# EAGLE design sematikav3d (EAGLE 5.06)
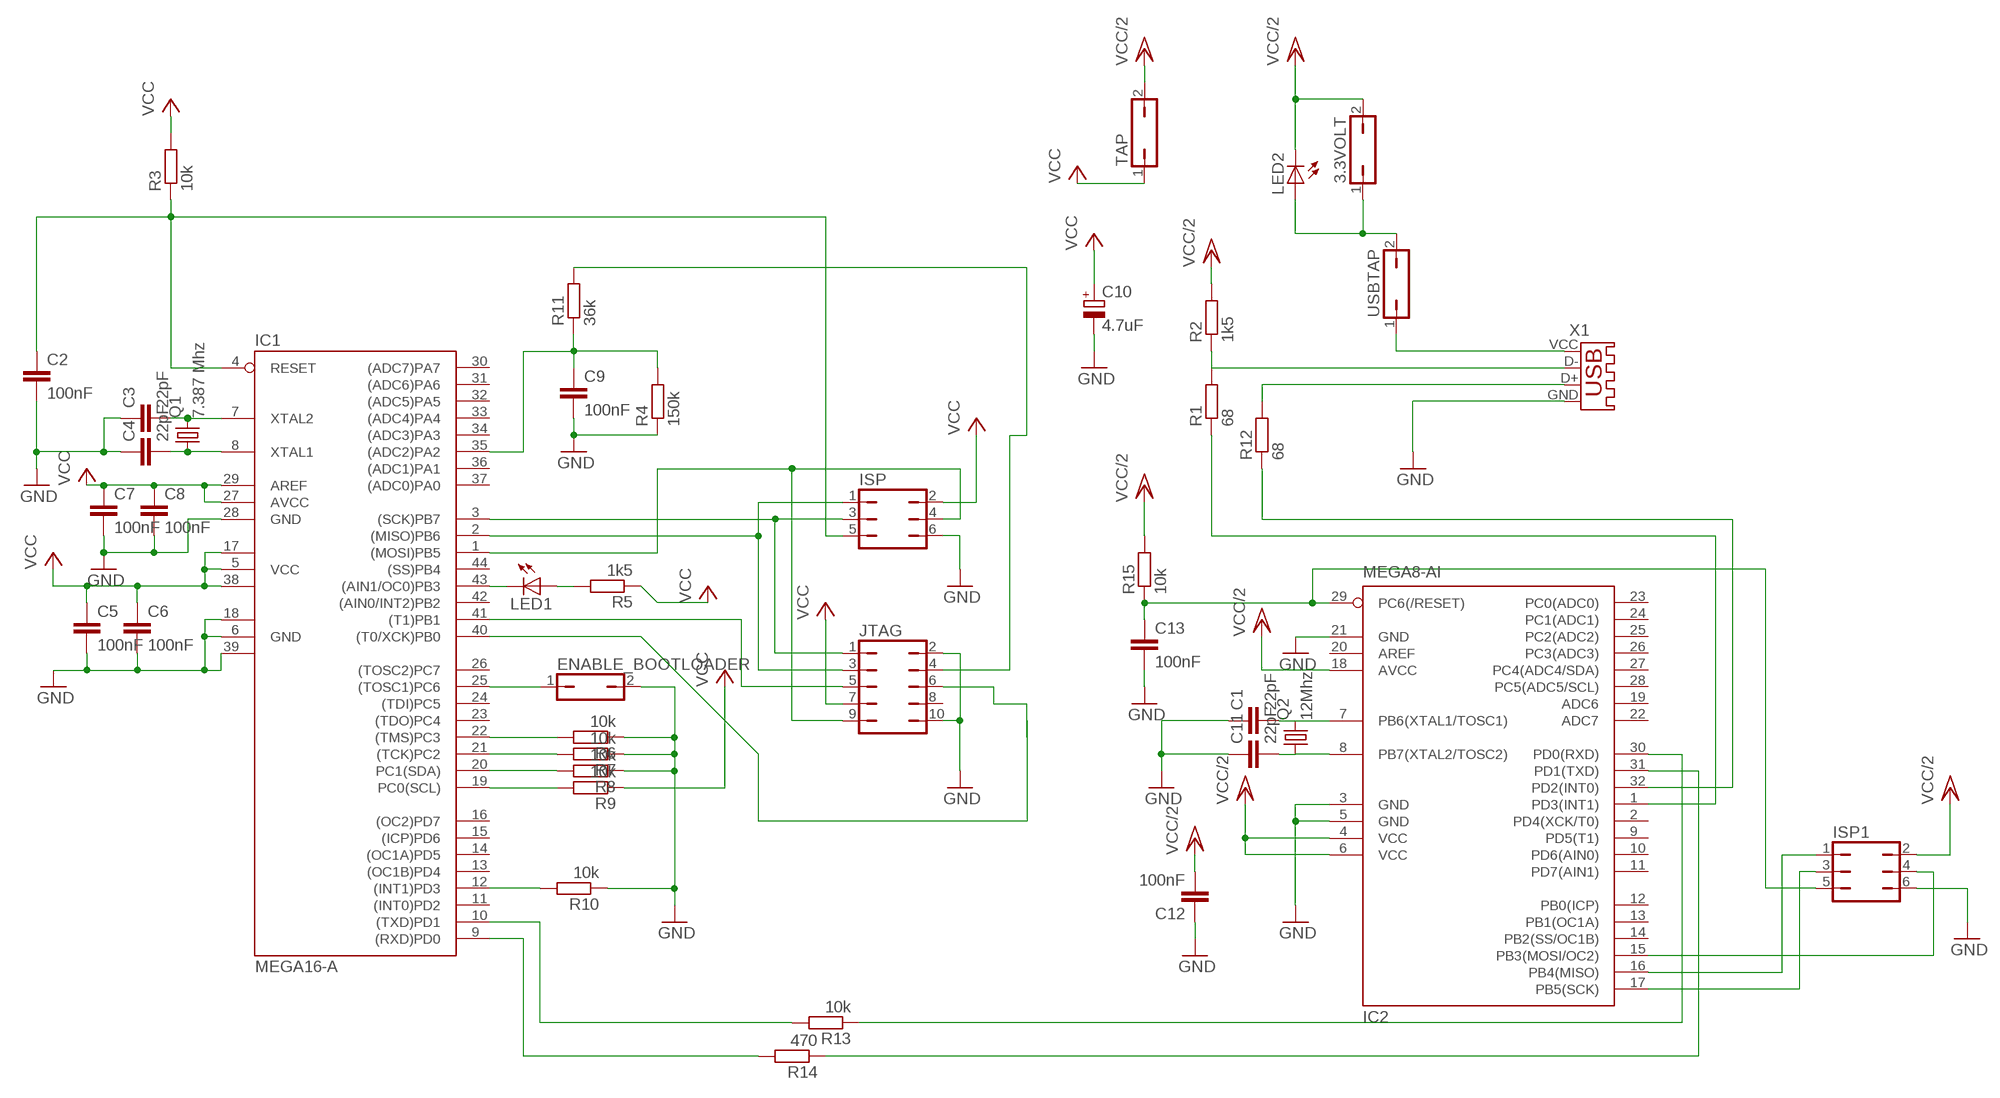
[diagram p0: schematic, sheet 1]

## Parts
3.3VOLT  JP1Q  [JP1]
C1  22pF  C-EUC1206  [C1206]
C2  100nF  C-EUC1206  [C1206]
C3  22pF  C-EUC1206  [C1206]
C4  22pF  C-EUC1206  [C1206]
C5  100nF  C-EUC1206  [C1206]
C6  100nF  C-EUC1206  [C1206]
C7  100nF  C-EUC1206  [C1206]
C8  100nF  C-EUC1206  [C1206]
C9  100nF  C-EUC1206  [C1206]
C10  4.7uF  CPOL-EUE2,5-6E  [E2,5-6E]
C11  22pF  C-EUC1206  [C1206]
C12  100nF  C-EUC1206  [C1206]
C13  100nF  C-EUC1206  [C1206]
ENABLE_BOOTLOADER  JP1Q  [JP1]
IC1  MEGA16-A  [TQFP44]
IC2  MEGA8-AI  [TQFP32-08]
ISP  JP3Q  [JP3Q]
ISP1  JP3Q  [JP3Q]
JTAG  JP5Q  [JP5Q]
LED1  LED3MM  [LED3MM]
LED2  LED5MM  [LED5MM]
Q1  7.387 Mhz  CRYSTALHC49U-V  [HC49U-V]
Q2  12Mhz  CRYSTALHC49U-V  [HC49U-V]
R1  68  R-EU_R1206  [R1206]
R2  1k5  R-EU_R1206  [R1206]
R3  10k  R-EU_R1206  [R1206]
R4  150k  R-EU_R1206  [R1206]
R5  1k5  R-EU_R1206  [R1206]
R6  10k  R-EU_R1206  [R1206]
R7  10k  R-EU_R1206  [R1206]
R8  10k  R-EU_R1206  [R1206]
R9  10k  R-EU_R1206  [R1206]
R10  10k  R-EU_R1206  [R1206]
R11  36k  R-EU_R1206  [R1206]
R12  68  R-EU_R1206  [R1206]
R13  10k  R-EU_R1206  [R1206]
R14  470  R-EU_R1206  [R1206]
R15  10k  R-EU_R1206  [R1206]
TAP  JP1Q  [JP1]
USBTAP  JP1Q  [JP1]
X1  USB-A003  [USB-A003]

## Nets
GND: C1.1 C2.2 C3.1 C4.1 C5.2 C6.2 C7.2 C8.2 C9.2 C10.- C11.1 C12.1 C13.2 ENABLE_BOOTLOADER.2 IC1.6(GND) IC1.18(GND1) IC1.28(GND) IC1.39(GND2) IC2.3(GND) IC2.5(GND) IC2.21(GND) ISP1.6 ISP.6 JTAG.2 JTAG.10 R4.1 R6.1 R7.1 R8.1 R10.1 X1.GND
N$1: 3.3VOLT.1 LED2.A USBTAP.2
N$2: IC2.1(PD3(INT1)) R1.1
N$3: R1.2 R2.1 X1.D-
N$4: R12.2 X1.D+
N$5: IC2.32(PD2(INT0)) R12.1
N$6: C11.2 IC2.8(PB7(XTAL2/TOSC2)) Q2.1
N$7: C1.2 IC2.7(PB6(XTAL1/TOSC1)) Q2.2
N$8: C2.1 IC1.4(RESET) ISP.5 R3.1
N$9: IC1.22((TMS)PC3) R6.2
N$10: C3.2 IC1.7(XTAL2) Q1.2
N$11: C4.2 IC1.8(XTAL1) Q1.1
N$12: C9.1 IC1.35((ADC2)PA2) R4.2 R11.1
N$13: IC1.21((TCK)PC2) R7.2
N$14: IC1.43((AIN1/OC0)PB3) LED1.K(C)
N$15: LED1.A R5.2
N$16: ENABLE_BOOTLOADER.1 IC1.25((TOSC1)PC6)
N$17: IC1.20(PC1(SDA)) R8.2
N$18: IC1.19(PC0(SCL)) R9.2
N$19: IC1.12((INT1)PD3) R10.2
N$20: IC1.1((MOSI)PB5) ISP.4 JTAG.9
N$21: IC1.3((SCK)PB7) ISP.3 JTAG.1
N$22: IC1.2((MISO)PB6) ISP.1 JTAG.3
N$24: IC1.41((T1)PB1) JTAG.5
N$27: IC1.40((T0/XCK)PB0) JTAG.6
N$28: JTAG.4 R11.2
N$37: USBTAP.1 X1.VCC
N$38: IC2.31(PD1(TXD)) R14.1
N$39: IC1.9((RXD)PD0) R14.2
N$40: IC2.30(PD0(RXD)) R13.1
N$41: IC1.10((TXD)PD1) R13.2
N$42: IC2.16(PB4(MISO)) ISP1.1
N$43: IC2.17(PB5(SCK)) ISP1.3
N$44: IC2.15(PB3(MOSI/OC2)) ISP1.4
N$45: C13.1 IC2.29(PC6(/RESET)) ISP1.5 R15.1
VCC: C5.1 C6.1 C7.1 C8.1 C10.+ IC1.5(VCC) IC1.17(VCC1) IC1.27(AVCC) IC1.29(AREF) IC1.38(VCC2) ISP.2 JTAG.7 R3.2 R5.1 R9.1 TAP.1
VCC/2: 3.3VOLT.2 C12.2 IC2.4(VCC) IC2.6(VCC) IC2.18(AVCC) ISP1.2 LED2.K(C) R2.2 R15.2 TAP.2
Unconnected: IC1.11((INT0)PD2) IC1.13((OC1B)PD4) IC1.14((OC1A)PD5) IC1.15((ICP)PD6) IC1.16((OC2)PD7) IC1.23((TDO)PC4) IC1.24((TDI)PC5) IC1.26((TOSC2)PC7) IC1.30((ADC7)PA7) IC1.31((ADC6)PA6) IC1.32((ADC5)PA5) IC1.33((ADC4)PA4) IC1.34((ADC3)PA3) IC1.36((ADC1)PA1) IC1.37((ADC0)PA0) IC1.42((AIN0/INT2)PB2) IC1.44((SS)PB4) IC2.2(PD4(XCK/T0)) IC2.9(PD5(T1)) IC2.10(PD6(AIN0)) IC2.11(PD7(AIN1)) IC2.12(PB0(ICP)) IC2.13(PB1(OC1A)) IC2.14(PB2(SS/OC1B)) IC2.19(ADC6) IC2.20(AREF) IC2.22(ADC7) IC2.23(PC0(ADC0)) IC2.24(PC1(ADC1)) IC2.25(PC2(ADC2)) IC2.26(PC3(ADC3)) IC2.27(PC4(ADC4/SDA)) IC2.28(PC5(ADC5/SCL)) JTAG.8

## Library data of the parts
3.3VOLT ENABLE_BOOTLOADER TAP USBTAP = jumper:JP1Q: JUMPER
C1-C9 C11-C13 = rcl:C-EU: CAPACITOR, European symbol
C10 = rcl:CPOL-EU: POLARIZED CAPACITOR, European symbol
IC1 = atmel:MEGA16: MICROCONTROLLER 16 Kbytes FLASH 1 kbytes SRAM 512 bytes EEPROM USART 8-channel 10 bit ADC Source: avr.lbr
IC2 = atmel:MEGA8: MICROCONTROLLER 8 Kbytes FLASH, 1 kbytes SRAM, 512 bytes EEPROM, USART, 6-channel 10 bit ADC, 2-channel 8 bit ADC Pin compatible with Atmega48, ATMega88, ATMega168 Source: avr.lbr
ISP ISP1 = jumper:JP3Q: JUMPER
JTAG = jumper:JP5Q: JUMPER
LED1 LED2 = led:LED: LED
Q1 Q2 = crystal:CRYSTAL: CRYSTAL
R1-R15 = resistor:R-EU_: RESISTOR, European symbol
X1 = con-usb_mate:USB-A003: USB connector

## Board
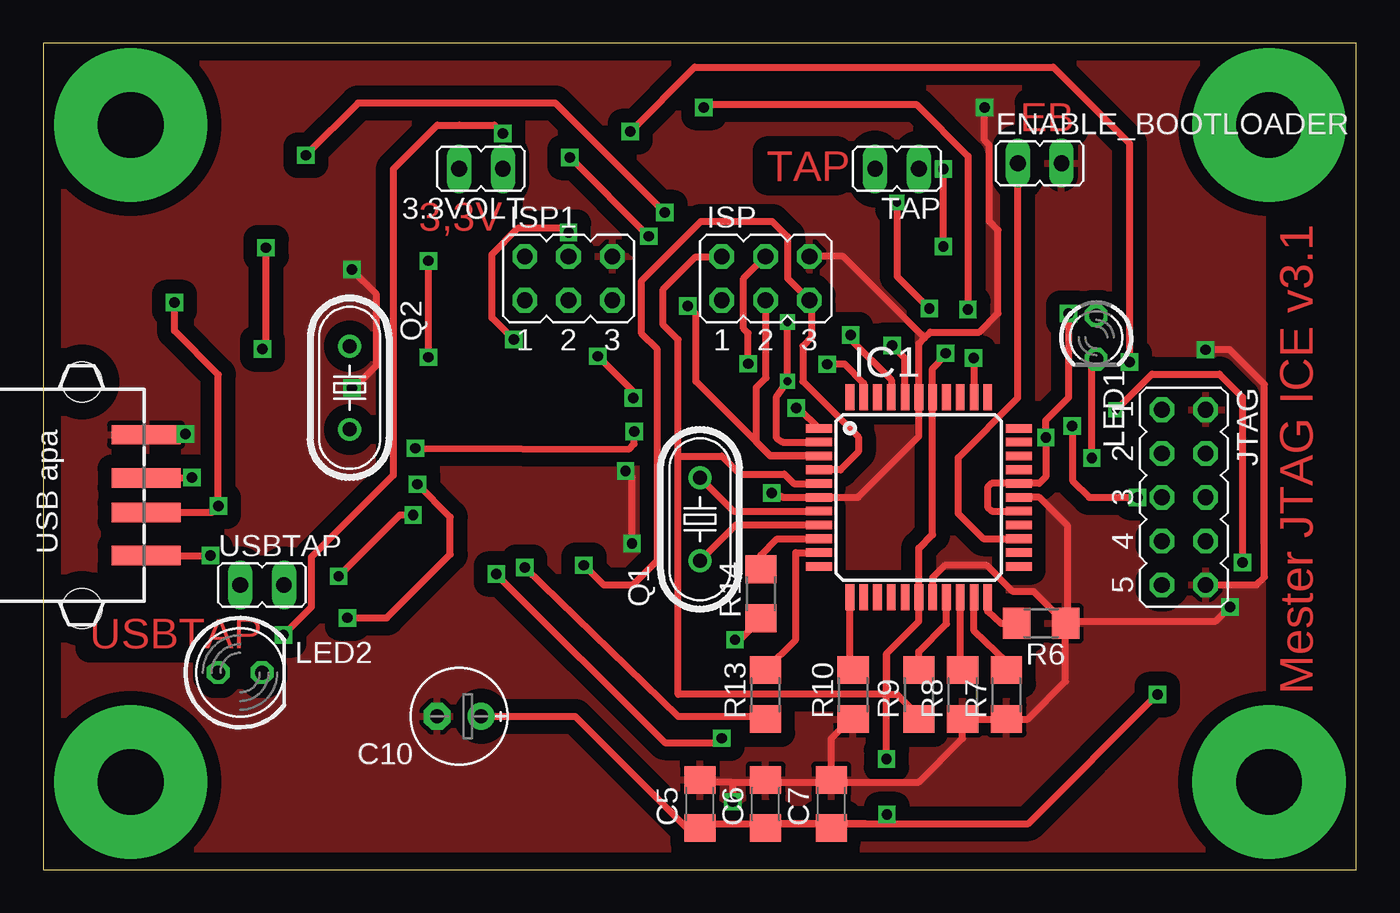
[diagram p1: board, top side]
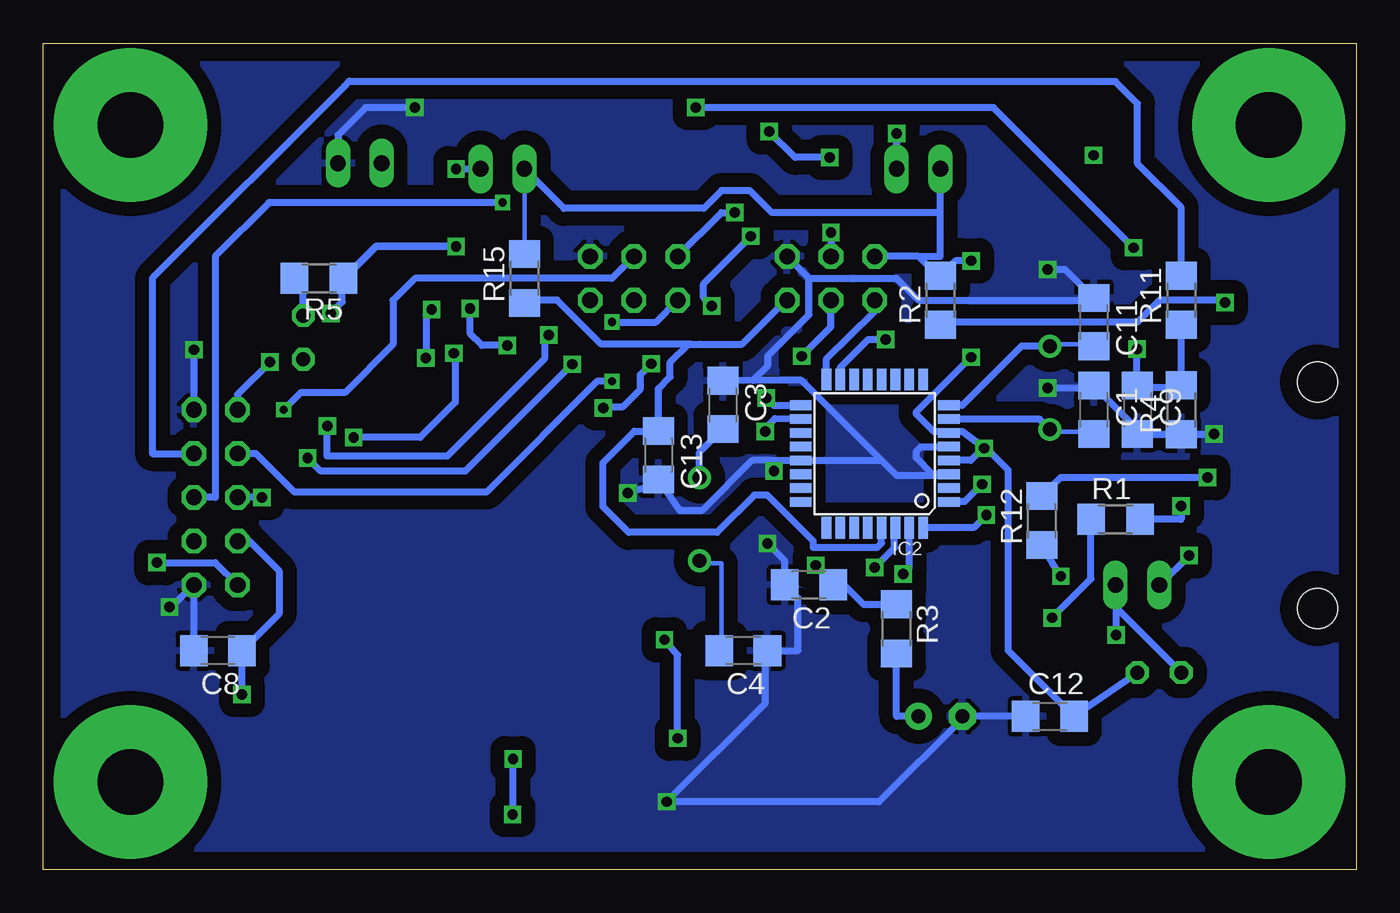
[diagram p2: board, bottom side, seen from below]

Size 76.18 x 47.93 mm. Coordinates in mm from the lower left corner, seen from the top.
Outline: 0,0 76.18,0 76.18,47.93 0,47.93 0,0
Copper layers (1*16): Top 0.035mm / dielectric 1.5mm / Bottom 0.035mm
Design rules "default *": minimum track width 10mil, minimum drill 19mil, track to track 8mil, track to pad 8mil, pad to pad 8mil, via to via 8mil, smd to smd 8mil, copper to edge 40mil, drill to drill 8mil, minimum pad ring 10mil, minimum via ring 8mil, stop-mask expansion 4mil, vias tented up to drill 0mil, thermal gap 10mil

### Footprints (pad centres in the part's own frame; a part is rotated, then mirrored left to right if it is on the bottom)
JP1 = drill 0.914 long: 1 0,-1.27; 2 0,1.27
C1206 = smd 1.6 x 1.8: 1 -1.4,0; 2 1.4,0
E2,5-6E = drill 0.813 pad 1.575 round: + -1.27,0 | drill 0.813 pad 1.575 octagon: - 1.27,0
TQFP44 = smd 1.5 x 0.5: 1 -5.8,4; 2 -5.8,3.2; 3 -5.8,2.4; 4 -5.8,1.6; 5 -5.8,0.8; 6 -5.8,0; 7 -5.8,-0.8; 8 -5.8,-1.6; 9 -5.8,-2.4; 10 -5.8,-3.2; 11 -5.8,-4; 23 5.8,-4; 24 5.8,-3.2; 25 5.8,-2.4; 26 5.8,-1.6; 27 5.8,-0.8; 28 5.8,0; 29 5.8,0.8; 30 5.8,1.6; 31 5.8,2.4; 32 5.8,3.2; 33 5.8,4 | smd 0.5 x 1.5: 12 -4,-5.8; 13 -3.2,-5.8; 14 -2.4,-5.8; 15 -1.6,-5.8; 16 -0.8,-5.8; 17 0,-5.8; 18 0.8,-5.8; 19 1.6,-5.8; 20 2.4,-5.8; 21 3.2,-5.8; 22 4,-5.8; 34 4,5.8; 35 3.2,5.8; 36 2.4,5.8; 37 1.6,5.8; 38 0.8,5.8; 39 0,5.8; 40 -0.8,5.8; 41 -1.6,5.8; 42 -2.4,5.8; 43 -3.2,5.8; 44 -4,5.8
TQFP32-08 = smd 1.27 x 0.559: 1 -4.293,2.8; 2 -4.293,2; 3 -4.293,1.2; 4 -4.293,0.4; 5 -4.293,-0.4; 6 -4.293,-1.2; 7 -4.293,-2; 8 -4.293,-2.8; 17 4.293,-2.8; 18 4.293,-2; 19 4.293,-1.2; 20 4.293,-0.4; 21 4.293,0.4; 22 4.293,1.2; 23 4.293,2; 24 4.293,2.8 | smd 0.559 x 1.27: 9 -2.8,-4.293; 10 -2,-4.293; 11 -1.2,-4.293; 12 -0.4,-4.293; 13 0.4,-4.293; 14 1.2,-4.293; 15 2,-4.293; 16 2.8,-4.293; 25 2.8,4.293; 26 2,4.293; 27 1.2,4.293; 28 0.4,4.293; 29 -0.4,4.293; 30 -1.2,4.293; 31 -2,4.293; 32 -2.8,4.293
JP3Q = drill 0.914 octagon: 1 -2.54,-1.27; 2 -2.54,1.27; 3 0,-1.27; 4 0,1.27; 5 2.54,-1.27; 6 2.54,1.27
JP5Q = drill 0.914 octagon: 1 -5.08,-1.27; 2 -5.08,1.27; 3 -2.54,-1.27; 4 -2.54,1.27; 5 0,-1.27; 6 0,1.27; 7 2.54,-1.27; 8 2.54,1.27; 9 5.08,-1.27; 10 5.08,1.27
LED3MM = drill 0.813 octagon: A -1.27,0; K 1.27,0
LED5MM = drill 0.813 octagon: A -1.27,0; K 1.27,0
HC49U-V = drill 0.813 round: 1 -2.413,0; 2 2.413,0
R1206 = smd 1.6 x 1.803: 1 -1.422,0; 2 1.422,0
USB-A003 = smd 1.12 x 4: D+ -1,14; D- 1,14; GND -3.5,14; VCC 3.5,14 | hole 2.3: -6.57,10.28; 6.57,10.28

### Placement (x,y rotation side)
3.3VOLT  25.4,40.64 90 top
C1  15.24,26.67 270 bottom
C2  31.75,16.51 180 bottom
C3  36.75,26.95 270 bottom
C4  35.56,12.7 180 bottom
C5  38.1,3.81 90 top
C6  41.91,3.81 90 top
C7  45.72,3.81 90 top
C8  66.04,12.7 180 bottom
C9  12.7,26.67 270 bottom
C10  24.13,8.89 180 top
C11  15.24,31.75 270 bottom
C12  17.78,8.89 0 bottom
C13  40.49,24.03 270 bottom
ENABLE_BOOTLOADER  57.81,40.97 270 top
IC1  50.8,21.59 0 top
IC2  27.94,24.13 180 bottom
ISP  41.91,34.29 0 top
ISP1  30.48,34.29 0 top
JTAG  66.17,21.59 270 top
LED1  61.09,30.86 270 top
LED2  11.43,11.43 0 top
Q1  38.1,20.32 90 top
Q2  17.78,27.94 270 top
R1  13.97,20.32 0 bottom
R2  24.13,33.02 90 bottom
R3  26.67,13.97 270 bottom
R4  10.16,26.67 90 bottom
R5  60.17,34.29 180 bottom
R6  57.89,14.29 180 top
R7  55.88,10.16 90 top
R8  53.34,10.16 90 top
R9  50.8,10.16 90 top
R10  46.99,10.16 90 top
R11  10.16,33.02 90 bottom
R12  18.24,20.24 90 bottom
R13  41.91,10.16 90 top
R14  41.63,16 90 top
R15  48.26,34.29 90 bottom
TAP  49.53,40.64 90 top
USBTAP  12.7,16.51 270 top
X1  -8.03,21.72 270 top

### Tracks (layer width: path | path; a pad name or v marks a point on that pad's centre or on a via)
GND  (via drill 0.6)
  Top 0.254: 38.1,5.08 C5.2 | 41.91,5.08 C6.2 | 46.99,8.89 R10.1 | 45.72,5.08 C7.2
  Top 0.406: 39.88,5.08 38.1,5.08 | 39.88,5.08 41.91,5.08 45.72,5.08 50.8,5.08 53.34,7.62 R8.1 R7.1 57.12,8.74 59.31,10.92 R6.1 | 46.99,8.89 45.72,7.62 C7.2 | v17.91,27.94 18.03,27.94 19.3,29.21 19.3,33.4 v17.91,34.8 | v40.01,3.94 40.01,4.95 39.88,5.08 | IC1.28 57.78,21.59 59.44,19.94 59.44,14.42 | R6.1 59.44,14.42 | R6.1 | IC1.18 51.6,16.93 52.32,17.65 54.74,17.65 56.26,16.13 57.47,16.13 R6.1 | v34.16,18.92 34.16,22.73 v33.78,23.11 | 59.44,14.42 68.02,14.42 v68.85,15.24 | v42.27,21.84 42.95,21.59 IC1.6 47.27,21.59 50.8,25.12 IC1.39 50.8,30.5 51.13,30.84 | JTAG.10 70.38,16.51 70.84,16.97 70.84,28.14 68.83,30.15 v67.44,30.15 | v8.25,25.27 6.03,25.27 X1.GND | v54.61,44.2 54.61,42.29 54.89,42.01 54.89,37.59 55.4,37.08 55.4,32.26 54.3,31.17 51.46,31.17 51.13,30.84 | ISP.6 46.41,35.56 51.13,30.84
  Bottom 0.254: 15.24,33.02 C11.1 | 12.7,25.4 C9.2 | R4.1 10.16,25.4 | 24.13,22.86 IC2.3 | 15.24,27.94 C1.1 | 34.29,12.7 C4.1
  Bottom 0.406: 15.24,33.02 25.4,33.02 26.67,34.29 31.75,34.29 | 31.75,34.29 ISP1.6 | 24.13,22.86 26.67,22.86 27.5,23.69 | C12.1 C10.- 22.86,8.76 27.69,3.94 v40.01,3.94 34.29,9.65 34.29,12.7 | IC2.3 24.58,22.93 25.53,23.88 25.53,24.26 25.27,24.51 23.67,24.51 IC2.5 | v17.91,27.94 15.24,27.94 | v17.91,34.8 16.89,34.8 C11.1 | C4.1 32.38,12.7 32.38,15.75 C2.2 33.15,17.91 v34.16,18.92 | 27.5,23.69 27.54,23.73 IC2.21 33.91,23.73 | C8.2 67.44,16.38 JTAG.10 68.71,15.24 v68.85,15.24 | 33.91,23.73 35.07,23.73 37.97,20.83 39.25,20.83 C13.2 40.89,22.23 v42.27,21.84 | v33.78,23.11 33.78,23.6 33.91,23.73 | 31.75,34.29 31.75,32.18 34.14,29.79 34.14,29.23 35,28.37 | 35,28.37 C3.1 | 27.5,23.69 32.18,28.37 35,28.37 | C9.2 12.68,25.25 R4.1 8.28,25.25 v8.25,25.27 | 12.7,25.4 12.7,25.53 C1.1 | v67.44,30.15 JTAG.2 | v54.61,44.2 57.48,44.2 59.08,42.6 ENABLE_BOOTLOADER.2
  pour Bottom (isolate 0.813): 0,0 76.2,0 76.2,48.26 0,48.26
  pour Top (isolate 0.813): 0,0 76.2,0 76.2,48.26 0,48.26
N$1  (via drill 0.6)
  Top 0.406: v26.67,42.7 26.19,43.18 24.13,43.18 22.86,43.18 20.32,40.64 20.32,22.86 20.29,22.86 15.57,18.14 15.57,15.24 v13.95,13.61
  Bottom 0.406: v26.67,42.7 3.3VOLT.1 | LED2.A 13.97,15.24 USBTAP.2 13.95,16.48 v13.95,13.61
N$2  (via drill 0.6)
  Top 0.406: v17.65,14.61 19.94,14.61 23.62,18.29 23.62,20.45 v21.72,22.35
  Bottom 0.406: R1.1 15.39,16.87 v17.65,14.61 | v21.72,22.35 22.73,21.34 IC2.1
N$3  (via drill 0.6)
  Top 0.406: v7.62,32.89 7.62,31.24 10.16,28.7 v10.16,21.08 9.79,20.72 X1.D-
  Bottom 0.254: R1.2 12.7,20.32 | 24.13,31.75 R2.1
  Bottom 0.406: 24.13,31.75 12.7,31.75 11.43,33.02 7.62,33.02 v7.62,32.89 | R1.2 10.16,20.32 v10.16,21.08
N$4  (via drill 0.6)
  Top 0.406: X1.D+ 8.62,22.72 v8.64,22.73
  Bottom 0.254: R12.2 19.05,21.59
  Bottom 0.406: v8.64,22.73 17.17,22.73 R12.2
N$5  (via drill 0.6)
  Top 0.406: v21.46,20.57 20.7,20.57 v17.14,17.02
  Bottom 0.406: IC2.32 22.2,19.84 v21.46,20.57 | v17.14,17.02 17.17,17.02 R12.1
N$6
  Bottom 0.254: C11.2 15.24,30.48 17.78,30.48 Q2.1
  Bottom 0.406: Q2.1 19.43,30.35 22.86,26.92 IC2.8
N$7
  Bottom 0.254: C1.2 15.24,25.4 17.78,25.4 Q2.2
  Bottom 0.406: IC2.7 18.38,26.13 Q2.2
N$8  (via drill 0.6)
  Top 0.406: v31.37,17.65 32.51,16.51 34.21,16.51 35.64,17.93 35.64,30.18 34.72,31.09 34.72,34.16 38.15,37.59 42.29,37.59 43.18,36.7 43.18,34.29 ISP.5 44.58,32.89 44.58,30.86 44.07,30.35 44.07,28.32 47.3,25.09 47.3,24.23 46.25,23.19 IC1.4 | IC1.4
  Bottom 0.406: v31.37,17.65 30.61,16.77 C2.1 29.72,16.51 28.57,15.37 26.7,15.37 R3.1
N$9
  Top 0.406: R6.2 55.56,14.29 54.8,14.99 54.8,15.73 IC1.22
N$10
  Top 0.406: IC1.7 40.04,20.79 Q1.2
  Bottom 0.406: Q1.2 38.1,24.2 C3.2
N$11
  Top 0.406: IC1.8 40.18,19.99 Q1.1
  Bottom 0.254: C4.2 36.83,12.7 36.83,17.78 38.1,17.78 Q1.1
N$12  (via drill 0.6)
  Top 0.406: IC1.35 54,29.13 v53.98,29.67 | v53.64,32.49 53.64,41.38 50.65,44.37 38.51,44.37 v38.33,44.2 | v12.93,36.07 12.93,30.4 v12.73,30.2
  Bottom 0.254: 12.7,27.94 C9.1 | R11.1 10.16,31.75 | R4.2 10.16,27.94
  Bottom 0.406: 10.16,27.94 12.7,27.94 | R4.2 R11.1 | v53.98,29.67 53.98,32.16 v53.64,32.49 | v38.33,44.2 21.06,44.2 v12.93,36.07 | v12.73,30.2 12.73,28.09 C9.1
N$13
  Top 0.406: R7.2 55.88,12.07 54,13.84 54,15.69 IC1.21
N$14  (via drill 0.6)
  Top 0.406: v60.83,23.88 60.83,29.34 LED1.K | v45.49,29.31 46.51,29.31 47.6,28.22 IC1.43 | IC1.43
  Bottom 0.406: v60.83,23.88 60.07,23.11 51.69,23.11 v45.49,29.31
N$15
  Bottom 0.406: R5.2 61.09,33.78 LED1.A
N$16
  Top 0.406: IC1.25 56.59,19.2 54.53,19.2 53.09,20.65 53.09,23.9 56.54,27.36 ENABLE_BOOTLOADER.1
N$17
  Top 0.254: 53.2,15.21 IC1.20 | R8.2 53.34,11.43
  Top 0.406: 53.2,15.21 53.2,11.72 R8.2
N$18
  Top 0.406: IC1.19 52.4,14.25 50.8,12.65 R9.2
N$19
  Top 0.406: IC1.12 46.8,11.77 R10.2
N$20  (via drill 0.48, 0.6)
  Top 0.406: v40.89,29.34 40.89,31.11 40.64,31.37 40.64,34.29 ISP.4 | v62.23,26.67 62.26,26.67 64.33,28.74 68.24,28.74 69.57,27.41 v69.57,17.8 | v43.69,26.77 43.92,26.67 IC1.1
  Bottom 0.406: ISP.4 43.18,34.29 54.61,34.29 55.88,33.02 55.88,30.46 58.67,27.66 61.24,27.66 v62.23,26.67 | v40.89,29.34 41.53,28.7 41.53,27.86 42.55,26.85 43.59,26.85 v43.69,26.77 | v69.57,17.8 66.19,17.8 JTAG.9
N$21  (via drill 0.6)
  Top 0.406: ISP.3 41.94,32.99 41.94,28.52 41.38,27.96 41.38,24.79 42.18,23.99 IC1.3 42.2,23.99 37.87,28.32 37.87,32.21 v37.39,32.69 | v35.13,36.73 v30.56,41.3 | v34.06,42.8 37.8,46.53 58.6,46.53 63.02,42.11 v63.02,29.44
  Bottom 0.406: v35.13,36.73 37.87,33.98 37.87,33.17 v37.39,32.69 | v30.56,41.3 32.56,41.3 v34.06,42.8 | v63.02,29.44 64.9,27.56 JTAG.1
N$22  (via drill 0.48)
  Top 0.406: v43.18,31.75 v43.18,28.32 42.55,27.43 42.55,25.02 42.9,24.79 IC1.2
  Bottom 0.406: ISP.1 40.64,31.75 v43.18,31.75 | v43.18,28.32 44.04,28.32 50.47,21.89 61.59,21.89 63.83,24.13 JTAG.3
N$24  (via drill 0.6)
  Top 0.406: v63.49,21.59 60.68,21.59 59.71,22.55 59.71,25.71 v59.69,25.73 | v46.84,31.01 46.84,30.76 49.2,28.4 IC1.41 | IC1.41
  Bottom 0.406: v63.49,21.59 JTAG.5 | v59.69,25.73 59.69,24.02 59.73,23.99 52.75,23.99 47.07,29.67 47.07,30.79 v46.84,31.01
N$27  (via drill 0.48, 0.6)
  Top 0.406: v49.53,38.68 49.55,38.66 49.55,34.39 v51.41,32.54 | IC1.40 50,29.65 v49.25,30.4
  Bottom 0.406: JTAG.6 66.19,21.59 66.19,35.56 63.07,38.68 v49.53,38.68 | v51.41,32.54 51.41,31.09 50.72,30.4 v49.25,30.4
N$28
  Bottom 0.254: R11.2 10.16,34.29
  Bottom 0.406: JTAG.4 69.85,24.13 69.85,34.29 58.7,45.44 | 58.7,45.44 58.42,45.72 | 58.7,45.44 58.45,45.7 13.98,45.7 12.7,44.42 12.7,40.95 10.16,38.4 R11.2
N$29  (via drill 3.81 pad 8.89)
  other vias: 71.12,43.18
N$30  (via drill 3.81 pad 8.89)
  other vias: 71.12,5.08
N$31  (via drill 3.81 pad 8.89)
  other vias: 5.08,43.18
N$32  (via drill 3.81 pad 8.89)
  other vias: 5.08,5.08
N$37  (via drill 0.6)
  Top 0.406: v9.7,18.21 X1.VCC
  Bottom 0.406: USBTAP.1 11.41,16.51 v9.7,18.21
N$38  (via drill 0.6)
  Top 0.406: v26.29,17.14 36.07,7.37 39.12,7.37 v39.37,7.62 | v40.13,13.34 40.41,13.34 R14.1
  Bottom 0.406: IC2.31 25.94,17.49 v26.29,17.14 | v39.37,7.62 39.37,12.45 v40.13,13.34
N$39
  Top 0.406: IC1.9 42.58,19.19 41.63,18.24 R14.2
N$40  (via drill 0.61)
  Top 0.254: 41.91,8.89 R13.1
  Top 0.406: v27.94,17.53 36.83,8.89 41.91,8.89
  Bottom 0.254: IC2.30 26.67,20.32
  Bottom 0.406: v27.94,17.53 26.8,18.67 26.8,19.78 IC2.30
N$41
  Top 0.406: IC1.10 43.66,18.39 43.66,13.34 R13.2
N$42
  Bottom 0.406: IC2.16 30.74,29.64 27.95,32.36 ISP1.1
N$43  (via drill 0.6)
  Top 0.406: v32.18,29.77 34.24,27.71 v34.24,27.36
  Bottom 0.406: v32.18,29.77 30.48,31.47 ISP1.3 | v34.24,27.36 33.81,26.93 IC2.17
N$44  (via drill 0.6)
  Top 0.406: v27.3,30.73 26.04,32 26.04,35.69 27.56,37.21 30.23,37.21 v30.48,36.96
  Bottom 0.406: v30.48,36.96 ISP1.4 | v27.3,30.73 28.32,30.73 29.95,29.11 29.94,29.1 IC2.15
N$45
  Bottom 0.254: R15.1 48.26,33.02
  Bottom 0.406: IC2.29 27.54,18.94 27.81,18.67 31.5,18.67 31.5,19.05 34.16,21.72 34.92,21.72 37.08,19.56 42.21,19.56 43.71,21.06 43.71,23.6 41.88,25.43 C13.1 40.49,27.89 39.8,28.57 39.8,29.41 38.73,30.48 | 38.73,30.48 43.81,30.48 46.35,33.02 48.11,33.02 R15.1 | 38.73,30.48 38.61,30.48 | 38.61,30.48 38.1,30.48 | ISP1.5 33.1,33.02 35.64,30.48 38.61,30.48
VCC  (via drill 0.6)
  Top 0.254: 50.8,8.89 R9.1
  Top 0.406: 50.8,8.89 49.53,10.16 48.92,10.16 | 48.92,10.16 36.83,10.16 36.83,23.98 | C10.+ 30.86,8.89 37.08,2.67 | 37.08,2.67 47.07,2.67 | 47.07,2.67 47.68,2.67 | 47.68,2.67 49.07,2.67 | 49.07,2.67 57.15,2.67 v64.64,10.16 | 50.8,14.4 IC1.17 50.8,18.62 | 48.92,12.52 48.92,10.16 | v15.24,41.43 18.26,44.45 29.72,44.45 v36.07,38.1 | IC1.5 43.55,22.39 43,22.94 40.41,22.94 39.37,23.98 36.83,23.98 | 51.6,19.44 51.6,27.29 IC1.38 51.59,27.4 51.59,29.06 52.35,29.82 v52.35,29.95 | 51.6,19.44 50.8,18.64 50.8,18.62 | IC1.27 55.03,20.79 54.79,21.03 54.79,22.17 55.02,22.4 56.59,22.4 IC1.29 56.61,22.4 57.78,22.4 58.17,22.78 v58.17,25.07 58.17,26.06 59.49,27.38 v59.49,32.26 | 51.6,19.44 51.6,19.42 50.8,18.62 | 50.8,14.4 50.8,18.62 | 48.92,12.52 50.8,14.4 | v48.92,6.43 48.92,12.52 | v48.95,3.2 48.95,2.79 49.07,2.67 | 37.08,2.67 37.34,2.41 C5.1 | C6.1 42.17,2.67 47.07,2.67 | C7.1 45.98,2.67 47.68,2.67 | v52.22,36.14 v52.22,40.64 | 36.83,23.98 36.83,30.73 35.97,31.6 35.97,33.65 37.85,35.53 39.34,35.53 ISP.2
  Bottom 0.254: R3.2 26.67,12.7 | C8.1 64.77,12.7
  Bottom 0.406: R3.2 26.67,8.89 C10.+ | v36.07,38.1 36.83,38.1 ISP.2 | v64.64,10.16 C8.1 62.46,14.88 62.46,17.3 64.21,19.05 JTAG.7 | v48.92,6.43 48.92,3.58 v48.95,3.2 | v52.22,40.64 TAP.1 | R5.1 56.9,36.14 v52.22,36.14 56.84,36.14 58.83,34.16 58.83,32.92 v59.49,32.26 | v58.17,25.07 54.3,25.07 52.27,27.1 52.27,29.87 v52.35,29.95
VCC/2  (via drill 0.6)
  Top 0.406: v22.35,29.72 v22.35,35.31 | v21.59,24.43 33.98,24.38 34.29,24.69 v34.29,25.4
  Bottom 0.254: 21.78,24.32 v21.59,24.43 | 24.13,25.4 IC2.6 | C12.2 16.51,8.89 | TAP.2 R15.2 48.26,35.56 | R2.2 24.13,34.29
  Bottom 0.406: LED2.K C12.2 20.19,12.7 20.19,23.16 21.35,24.32 21.78,24.32 22.37,23.73 IC2.4 | 24.13,34.29 25.4,35.56 | 25.4,35.56 ISP1.2 | 24.13,38.1 24.13,35.56 25.4,35.56 | 24.13,38.1 3.3VOLT.2 | 24.13,38.1 33.91,38.1 35.18,39.37 36.83,39.37 37.85,38.35 45.97,38.35 TAP.2 | v21.59,24.43 22.86,25.4 24.13,25.4 24.51,25.4 25.53,26.42 25.53,26.54 v22.35,29.72 | v22.35,35.31 23.27,35.31 R2.2 | IC2.18 33.74,26.16 34.29,25.6 v34.29,25.4

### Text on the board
Top: EB | TAP | 3,3V | USBTAP | Mester JTAG ICE v3.1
